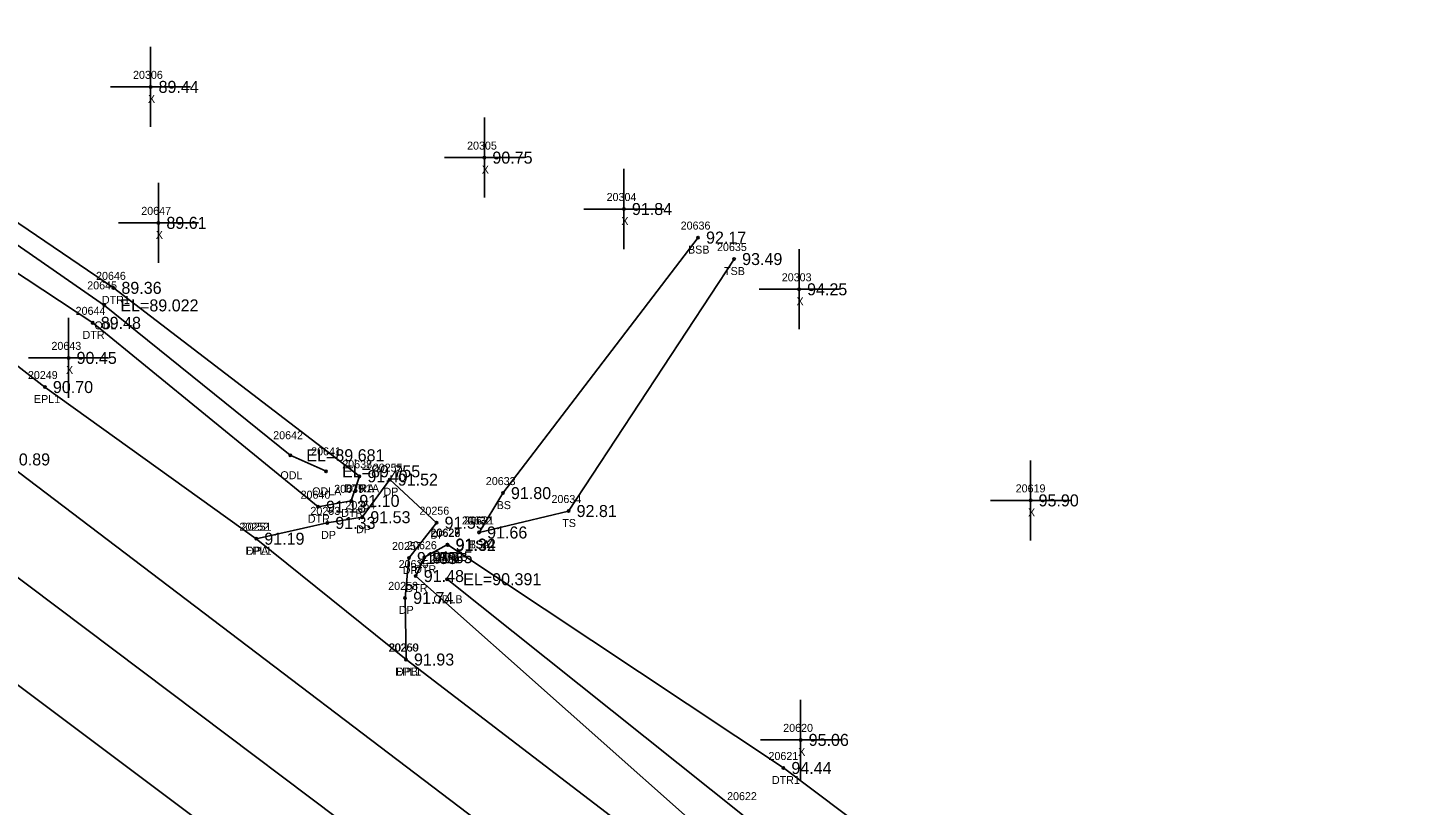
# Model space of a CAD drawing. Extents: x 2530197 to 2532051, y 935230 to 936631.
# Drawn here: x 2531847.5 to 2532021.5, y 936230.9 to 936328 of the extents above; entities that cross this region are included whole.
import ezdxf

# ---------------------------------------------------------------- set-up
doc = ezdxf.new("R2010")
doc.units = 0
for name, color, linetype in [('RD_DTM_BkLn1', 7, 'Continuous'), ('RD_DTM_BkLn2', 7, 'Continuous'), ('RD_DTM_BkLn_txCode', 7, 'Continuous'), ('RD_EX_Driveway', 7, 'Continuous'), ('RD_EX_Driveway_txCode', 7, 'Continuous'), ('RD_EX_H2O', 7, 'Continuous'), ('RD_EX_H2O_txCode', 7, 'Continuous'), ('RD_EX_Misc', 7, 'Continuous'), ('RD_EX_Misc_txCode', 7, 'Continuous'), ('RD_EX_Road', 7, 'Continuous'), ('RD_EX_Road_txCode', 7, 'Continuous'), ('RD_EX_TX_Driveway_ELEV', 7, 'Continuous'), ('RD_EX_TX_H2O_ELEV', 7, 'Continuous'), ('RD_EX_TX_Misc_ELEV', 7, 'Continuous'), ('RD_EX_TX_Road_ELEV', 7, 'Continuous'), ('RD_HC_Survey_ELEV', 7, 'Continuous'), ('RD_SMD_Locator', 7, 'Continuous')]:
    doc.layers.add(name, color=color, linetype=linetype)

msp = doc.modelspace()

# ---------------------------------------------------------------- linework, layer by layer
at = {"layer": 'RD_DTM_BkLn1'}
for points in [[(2531766.68, 936333.11), (2531794.16, 936312.25), (2531844.23, 936274.13), (2531924.38, 936213.25), (2532005.14, 936152.12)], [(2531839.12, 936251.81), (2531841.44, 936249.51), (2531884.63, 936217.15), (2531903.05, 936202.75), (2531912.55, 936196.67)]]:
    msp.add_lwpolyline(points, dxfattribs=at)
at = {"layer": 'RD_DTM_BkLn2'}
for points in [[(2531903.84, 936265), (2531906.82, 936269.92), (2531931.19, 936301.84)], [(2531903.84, 936265), (2531915.02, 936267.68), (2531935.7, 936299.16)]]:
    msp.add_lwpolyline(points, dxfattribs=at)
at = {"layer": 'RD_EX_Driveway'}
msp.add_lwpolyline([(2531876.01, 936264.22), (2531884.88, 936266.2), (2531889.25, 936266.91), (2531892.68, 936271.6), (2531898.53, 936266.22), (2531895.08, 936261.81), (2531894.6, 936256.83), (2531894.71, 936249.13)], dxfattribs=at)
at = {"layer": 'RD_EX_H2O'}
for points in [[(2531884.72, 936272.64), (2531880.26, 936274.65), (2531857.03, 936293.37), (2531824.14, 936316.16), (2531815.27, 936323.11)], [(2531888.89, 936272.02), (2531887.88, 936268.95), (2531883.72, 936268.22), (2531855.58, 936291.19), (2531822.13, 936313.28), (2531815.27, 936323.11)], [(2531888.89, 936272.02), (2531858.16, 936295.56), (2531826.03, 936317.37), (2531815.27, 936323.11)], [(2532013.59, 936164.05), (2531933.99, 936225.75), (2531895.93, 936259.56), (2531897, 936261.91), (2531899.89, 936263.49), (2531899.92, 936263.44)], [(2532021.52, 936175.64), (2531941.85, 936235.58), (2531899.92, 936263.44)], [(2532016.69, 936168.44), (2531936.96, 936229.56), (2531899.85, 936259.16)]]:
    msp.add_lwpolyline(points, dxfattribs=at)
at = {"layer": 'RD_EX_Misc'}
for p, q in [((2531862.8, 936315.67), (2531862.8, 936325.67)), ((2531857.8, 936320.67), (2531867.8, 936320.67)), ((2531904.5, 936306.83), (2531904.5, 936316.83)), ((2531899.5, 936311.83), (2531909.5, 936311.83)), ((2531921.93, 936300.41), (2531921.93, 936310.41)), ((2531863.78, 936298.68), (2531863.78, 936308.68)), ((2531916.93, 936305.41), (2531926.93, 936305.41)), ((2531858.78, 936303.68), (2531868.78, 936303.68)), ((2531943.81, 936290.38), (2531943.81, 936300.38)), ((2531938.81, 936295.38), (2531948.81, 936295.38)), ((2531852.56, 936281.81), (2531852.56, 936291.81)), ((2531847.56, 936286.81), (2531857.56, 936286.81)), ((2531972.73, 936264.01), (2531972.73, 936274.01)), ((2531967.73, 936269.01), (2531977.73, 936269.01)), ((2531944.01, 936234.09), (2531944.01, 936244.09)), ((2531939.01, 936239.09), (2531949.01, 936239.09))]:
    msp.add_line(p, q, dxfattribs=at)
at = {"layer": 'RD_EX_Road'}
for points in [[(2531788.67, 936375.53), (2531784.05, 936361.55), (2531786.68, 936344.28), (2531790.66, 936334.1), (2531795.41, 936327.11), (2531801.08, 936320.84), (2531849.6, 936283.17), (2531876.01, 936264.22), (2531894.71, 936249.13), (2531930.69, 936221.59), (2532010.91, 936160.51)], [(2531730.37, 936304.55), (2531747.09, 936311.1), (2531758.83, 936311.42), (2531770.03, 936309.95), (2531779.92, 936307.38), (2531789.77, 936300.82), (2531836.93, 936266.34), (2531918.06, 936205.29), (2531926.11, 936199.32), (2531961.6, 936172.59), (2531979.77, 936158.9), (2531999.31, 936144.02)]]:
    msp.add_lwpolyline(points, dxfattribs=at)
at = {"layer": 'RD_SMD_Locator'}
for centre in [(2531862.8, 936320.67), (2531904.5, 936311.83), (2531921.93, 936305.41), (2531863.78, 936303.68), (2531931.19, 936301.84), (2531935.7, 936299.16), (2531858.16, 936295.56), (2531943.81, 936295.38), (2531857.03, 936293.37), (2531855.58, 936291.19), (2531852.56, 936286.81), (2531849.6, 936283.17), (2531880.26, 936274.65), (2531884.72, 936272.64), (2531888.89, 936272.02), (2531888.89, 936272.02), (2531892.68, 936271.6), (2531887.88, 936268.95), (2531906.82, 936269.92), (2531972.73, 936269.01), (2531883.72, 936268.22), (2531889.25, 936266.91), (2531915.02, 936267.68), (2531884.88, 936266.2), (2531898.53, 936266.22), (2531903.84, 936265), (2531903.84, 936265), (2531876.01, 936264.22), (2531876.01, 936264.22), (2531899.89, 936263.49), (2531899.92, 936263.44), (2531899.92, 936263.44), (2531895.08, 936261.81), (2531897, 936261.91), (2531895.93, 936259.56), (2531899.85, 936259.16), (2531894.6, 936256.83), (2531894.71, 936249.13), (2531894.71, 936249.13), (2531944.01, 936239.09), (2531941.85, 936235.58)]:
    msp.add_circle(centre, 0.15, dxfattribs=at)

# ---------------------------------------------------------------- texts
at = {"layer": 'RD_DTM_BkLn_txCode'}
for s, p in [('20636', (2531929.02, 936302.84)), ('BSB', (2531929.94, 936299.84)), ('20635', (2531933.56, 936300.16)), ('TSB', (2531934.44, 936297.16)), ('20633', (2531904.68, 936270.92)), ('BS', (2531906.04, 936267.92)), ('20634', (2531912.88, 936268.68)), ('20632', (2531901.69, 936266)), ('20631', (2531901.98, 936266)), ('TS', (2531914.23, 936265.68)), ('TSA', (2531902.55, 936263)), ('BSA', (2531902.57, 936263))]:
    msp.add_text(s, height=1, dxfattribs=at).set_placement(p)
at = {"layer": 'RD_EX_Driveway_txCode'}
for s, p in [('20255', (2531890.56, 936272.6)), ('DP', (2531891.9, 936269.6)), ('20254', (2531887.14, 936267.91)), ('20253', (2531882.77, 936267.2)), ('20256', (2531896.39, 936267.22)), ('20252', (2531873.9, 936265.22)), ('DP', (2531884.1, 936264.2)), ('DP', (2531888.47, 936264.91)), ('DP', (2531897.75, 936264.22)), ('20257', (2531892.96, 936262.81)), ('DPA', (2531874.75, 936262.22)), ('DP', (2531894.3, 936259.81)), ('20258', (2531892.49, 936257.83)), ('DP', (2531893.82, 936254.83)), ('20259', (2531892.6, 936250.13)), ('DPB', (2531893.46, 936247.13))]:
    msp.add_text(s, height=1, dxfattribs=at).set_placement(p)
at = {"layer": 'RD_EX_H2O_txCode'}
for s, p in [('20645', (2531854.89, 936295.37)), ('20646', (2531855.99, 936296.56)), ('20644', (2531853.44, 936292.19)), ('DTR1', (2531856.72, 936293.56)), ('ODL', (2531855.79, 936290.37)), ('DTR', (2531854.31, 936289.19)), ('20642', (2531878.12, 936276.65)), ('20641', (2531882.86, 936274.64)), ('20637', (2531886.75, 936273.02)), ('20638', (2531886.75, 936273.02)), ('ODL', (2531879.02, 936271.65)), ('ODLA', (2531882.99, 936269.64)), ('20639', (2531885.74, 936269.95)), ('DTR1A', (2531886.97, 936270.02)), ('DTRA', (2531887.13, 936270.02)), ('20640', (2531881.54, 936269.22)), ('DTR', (2531882.45, 936266.22)), ('DTR', (2531886.62, 936266.95)), ('20627', (2531897.75, 936264.49)), ('20628', (2531897.78, 936264.44)), ('20629', (2531897.78, 936264.44)), ('20626', (2531894.84, 936262.91)), ('20625', (2531893.79, 936260.56)), ('20630', (2531897.67, 936261.16)), ('DTR1B', (2531898.01, 936261.44)), ('DTRB', (2531898.18, 936261.44)), ('DTR', (2531898.62, 936261.49)), ('DTR', (2531895.73, 936259.91)), ('DTR', (2531894.66, 936257.56)), ('ODLB', (2531898.13, 936256.16)), ('20621', (2531939.99, 936236.58)), ('DTR1', (2531940.42, 936233.58)), ('20622', (2531934.82, 936231.56))]:
    msp.add_text(s, height=1, dxfattribs=at).set_placement(p)
at = {"layer": 'RD_EX_Misc_txCode'}
for s, p in [('20306', (2531860.61, 936321.67)), ('X', (2531862.48, 936318.67)), ('20305', (2531902.34, 936312.83)), ('X', (2531904.18, 936309.83)), ('20304', (2531919.77, 936306.41)), ('20647', (2531861.64, 936304.68)), ('X', (2531921.61, 936303.41)), ('X', (2531863.46, 936301.68)), ('20303', (2531941.65, 936296.38)), ('X', (2531943.49, 936293.38)), ('20643', (2531850.42, 936287.81)), ('X', (2531852.24, 936284.81)), ('20619', (2531970.87, 936270.01)), ('X', (2531972.41, 936267.01)), ('20620', (2531941.83, 936240.09)), ('X', (2531943.7, 936237.09))]:
    msp.add_text(s, height=1, dxfattribs=at).set_placement(p)
at = {"layer": 'RD_EX_Road_txCode'}
for s, p in [('20249', (2531847.48, 936284.17)), ('EPL1', (2531848.23, 936281.17)), ('20251', (2531874.18, 936265.22)), ('EPL1', (2531874.64, 936262.22)), ('20260', (2531892.53, 936250.13)), ('EPL1', (2531893.34, 936247.13))]:
    msp.add_text(s, height=1, dxfattribs=at).set_placement(p)
at = {"layer": 'RD_EX_TX_Driveway_ELEV'}
for s, p in [('91.52', (2531893.68, 936270.85)), ('91.33', (2531885.88, 936265.45)), ('91.53', (2531890.25, 936266.16)), ('91.55', (2531899.53, 936265.47)), ('91.19', (2531877.01, 936263.47)), ('91.55', (2531896.08, 936261.06)), ('91.74', (2531895.6, 936256.08)), ('91.93', (2531895.71, 936248.38))]:
    msp.add_text(s, height=1.5, dxfattribs=at).set_placement(p)
at = {"layer": 'RD_EX_TX_H2O_ELEV'}
for s, p in [('89.36', (2531859.16, 936294.81)), ('EL=89.022', (2531859.03, 936292.62)), ('89.48', (2531856.58, 936290.44)), ('EL=89.681', (2531882.26, 936273.9)), ('EL=89.755', (2531886.72, 936271.89)), ('91.40', (2531889.89, 936271.27)), ('91.40', (2531889.89, 936271.27)), ('91.13', (2531884.72, 936267.47)), ('91.10', (2531888.88, 936268.2)), ('91.34', (2531900.89, 936262.74)), ('91.32', (2531900.92, 936262.69)), ('91.32', (2531900.92, 936262.69)), ('91.35', (2531898, 936261.16)), ('91.48', (2531896.93, 936258.81)), ('EL=90.391', (2531901.85, 936258.41)), ('94.44', (2531942.85, 936234.83))]:
    msp.add_text(s, height=1.5, dxfattribs=at).set_placement(p)
at = {"layer": 'RD_EX_TX_Misc_ELEV'}
for s, p in [('89.44', (2531863.8, 936319.92)), ('90.75', (2531905.5, 936311.08)), ('91.84', (2531922.93, 936304.66)), ('89.61', (2531864.78, 936302.93)), ('92.17', (2531932.19, 936301.09)), ('93.49', (2531936.7, 936298.41)), ('94.25', (2531944.81, 936294.63)), ('90.45', (2531853.56, 936286.06)), ('91.80', (2531907.82, 936269.17)), ('95.90', (2531973.73, 936268.26)), ('92.81', (2531916.02, 936266.93)), ('91.66', (2531904.84, 936264.25)), ('91.66', (2531904.84, 936264.25)), ('95.06', (2531945.01, 936238.34))]:
    msp.add_text(s, height=1.5, dxfattribs=at).set_placement(p)
at = {"layer": 'RD_EX_TX_Road_ELEV'}
for s, p in [('90.70', (2531850.6, 936282.42)), ('91.19', (2531877.01, 936263.47)), ('91.93', (2531895.71, 936248.38))]:
    msp.add_text(s, height=1.5, dxfattribs=at).set_placement(p)
at = {"layer": 'RD_HC_Survey_ELEV'}
msp.add_text('90.89', height=1.5, dxfattribs=at).set_placement((2531845.23, 936273.38))

doc.saveas('drawing.dxf')
